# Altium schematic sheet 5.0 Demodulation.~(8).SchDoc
size A4; SheetNumber: 5; SheetTotal: 7
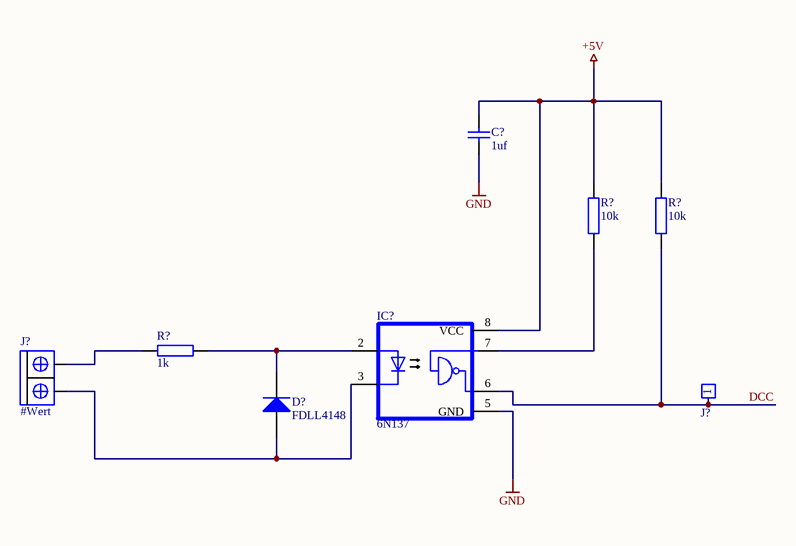
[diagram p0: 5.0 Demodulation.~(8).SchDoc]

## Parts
(Parts that share a designator on the sheet are numbered #1, #2 ... from top to bottom, then left to right.)
C?  1uf  [C_SMD_0805]
D?  FDLL4148  [D_SMD_1206]
IC?  6N137  [DIP-8]
J?#1  #Wert  [J_THT_Printklemme 2x]
J?#2  #Wert  [SIP-1]  (value not drawn)
R?#1  10k  [R_SMD_0805]
R?#2  10k  [R_SMD_0805]
R?#3  1k  [R_SMD_0805]

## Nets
+5V: C?.1 IC?.8(VCC) R?#1.2 R?#2.2
GND: C?.2 IC?.5(GND)
DCC: IC?.6(VO) J?#2.1 R?#2.1
NetD?_1: D?.1(A) IC?.3(LED-) J?#1.1
NetD?_2: D?.2(K) IC?.2(LED+) R?#3.2
NetIC?_7: IC?.7(VE) R?#1.1
NetJ?#1_2: J?#1.2 R?#3.1

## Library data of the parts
C? = C_SMD_KO: Kondensator SMD Universal, Keramik, Folie, usw.
D? = D_SMD_Silizium: Diode SMD Silizium; Spannung For.: 0,7V
IC? = IC_6N137: Optokoppler
J?#1 = J_THT_Printklemme 2x: Printklemme
J?#2 = J_THT_CON1: Stecker
R?#1-R?#3 = R_SMD_Widerstand: Widerstand SMD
